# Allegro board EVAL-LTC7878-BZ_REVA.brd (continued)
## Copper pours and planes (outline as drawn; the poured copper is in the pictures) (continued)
UNNAMED_4_IND_I84_N1 on TOP: 96.2,88.98 96.22,89.01 96.25,89.03 96.85,89.03 96.89,89.01 96.9,88.98 96.9,87.94 96.89,87.9 96.85,87.88 96.25,87.88 96.22,87.9 96.2,87.94
UNNAMED_4_IND_I84_N1 on TOP, BOTTOM: 95.76,111.12 95.76,93.6 83.44,93.6 83.44,111.12
UNNAMED_4_NCTESTPAD_I106_N1 on TOP: 105.76,72.26 107.6,72.26
UNNAMED_4_RES_I65_N1 on TOP: 72.01,97.36 72.02,97.39 72.06,97.41 73.36,97.41 73.39,97.39 73.41,97.36 73.41,95.17 73.39,95.14 73.36,95.12 72.06,95.12 72.02,95.14 72.01,95.17
UNNAMED_4_RES_I79_N1 on TOP: 112.01,96.47 112.03,96.51 112.06,96.52 113.26,96.52 113.28,96.52 113.3,96.51 113.52,96.28 113.53,96.26 113.54,96.24 113.54,95.3 113.52,95.26 113.49,95.25 112.06,95.25 112.03,95.26 112.01,95.3
UNNAMED_4_RES_I108_N1 on TOP: 115.14,98.17 115.17,98.16 115.19,98.12 115.19,97.56 115.19,97.54 115.17,97.52 114.31,96.66 114.3,96.65 114.28,96.65 113.84,96.65 113.81,96.66 113.79,96.7 113.79,98.12 113.81,98.16 113.84,98.17
UNNAMED_4_RES_I108_N1 on TOP: 114.38,103.76 114.41,103.74 114.43,103.71 114.43,102.54 114.41,102.5 114.38,102.49 113.72,102.49 113.68,102.5 113.67,102.54 113.67,103.71 113.68,103.74 113.72,103.76
UNNAMED_5_ADLTC7878V2_I47_BG1 on TOP: 73.1,33.91 73.14,33.89 73.15,33.86 73.15,32.69 73.14,32.65 73.1,32.64 72.19,32.64 72.15,32.65 72.14,32.69 72.14,33.86 72.15,33.89 72.19,33.91
UNNAMED_5_ADLTC7878V2_I47_BG2 on TOP: 106.48,32.64 106.44,32.65 106.43,32.69 106.43,33.86 106.44,33.89 106.48,33.91 107.14,33.91 107.17,33.89 107.19,33.86 107.19,32.69 107.17,32.65 107.14,32.64
UNNAMED_5_ADLTC7878V2_I47_BOOST1 on TOP: 92.2,24.21 92.22,24.24 92.25,24.26 93.58,24.26 93.6,24.25 93.61,24.24 93.71,24.14 93.73,24.13 93.75,24.13 94.49,24.13 94.51,24.13 94.53,24.12 94.73,23.92 94.74,23.9 94.74,23.88 94.74,23.29 94.73,23.26 94.69,23.24 94.13,23.24 94.11,23.24 94.09,23.26 93.87,23.48 93.85,23.49 93.83,23.5 92.25,23.5 92.22,23.51 92.2,23.55
UNNAMED_5_ADLTC7878V2_I47_CSN on TOP: 102.86,24.38 104.66,24.38
UNNAMED_5_ADLTC7878V2_I47_CSP on TOP: 104.27,22.1 104.27,20.32 102.11,20.32 101.73,20.7 101.73,21.34 102.11,21.72 103.38,21.72 103.38,22.1
UNNAMED_5_ADLTC7878V2_I47_EXTVCC on TOP: 89.41,18.36 89.42,18.4 89.46,18.41 91.13,18.41 91.15,18.41 91.17,18.4 91.3,18.27 91.31,18.26 91.31,18.24 91.31,17.27 90.81,16.76 90.81,15.88 90.04,15.88 90.04,16.89 89.46,16.89 89.42,16.91 89.41,16.94
UNNAMED_5_ADLTC7878V2_I47_EXTVCC on TOP: 77.31,19.3 79.16,19.3
UNNAMED_5_ADLTC7878V2_I47_ISNSD on TOP: 95.83,25.4 95.87,25.39 95.89,25.35 95.89,24.31 95.87,24.27 95.83,24.26 95.53,24.26 95.51,24.26 95.49,24.27 95.07,24.69 95.06,24.7 95.06,24.72 95.06,25.35 95.07,25.39 95.11,25.4
UNNAMED_5_ADLTC7878V2_I47_ITHB on TOP: 97.66,13.28 97.68,13.32 97.71,13.34 98.37,13.34 98.41,13.32 98.42,13.28 98.42,12.47 98.42,12.45 98.41,12.44 98.18,12.21 98.17,12.2 98.15,12.19 97.71,12.19 97.68,12.21 97.66,12.24
UNNAMED_5_ADLTC7878V2_I47_MODE on TOP: 104.39,15.95 104.41,15.99 104.44,16 105.36,16 105.4,15.99 105.41,15.95 105.41,15.35 105.4,15.32 105.36,15.3 104.44,15.3 104.41,15.32 104.39,15.35
UNNAMED_5_ADLTC7878V2_I47_PGOOD on TOP: 95.63,13.28 95.65,13.32 95.68,13.34 96.34,13.34 96.38,13.32 96.39,13.28 96.39,12.24 96.38,12.21 96.34,12.19 95.68,12.19 95.65,12.21 95.63,12.24
UNNAMED_5_ADLTC7878V2_I47_PGOOD on TOP: 77.18,10.79 79.03,10.79
UNNAMED_5_ADLTC7878V2_I47_PHASMD on TOP: 104.39,16.97 104.41,17 104.44,17.02 105.36,17.02 105.4,17 105.41,16.97 105.41,16.31 105.4,16.27 105.36,16.26 104.44,16.26 104.41,16.27 104.39,16.31
UNNAMED_5_ADLTC7878V2_I47_SETCUR on TOP: 101.73,20.02 101.74,20.05 101.78,20.07 102.95,20.07 102.98,20.05 103,20.02 103,19.36 102.98,19.32 102.95,19.3 101.78,19.3 101.74,19.32 101.73,19.36
UNNAMED_5_ADLTC7878V2_I47_SW1 on TOP: 94.61,27.64 94.63,27.67 94.67,27.69 95.77,27.69 95.81,27.67 95.82,27.64 95.82,26.85 95.81,26.81 95.77,26.8 94.89,26.8 94.87,26.8 94.85,26.81 94.63,27.04 94.62,27.05 94.61,27.07
UNNAMED_5_ADLTC7878V2_I47_SW1 on TOP: 93.34,25.22 93.36,25.26 93.4,25.27 94.75,25.27 94.79,25.26 94.8,25.22 94.8,24.62 94.81,24.6 94.82,24.58 94.85,24.55 94.87,24.53 94.87,24.51 94.87,24.44 94.85,24.4 94.82,24.38 93.85,24.38 93.83,24.39 93.82,24.4 93.72,24.5 93.7,24.51 93.68,24.51 93.4,24.51 93.36,24.53 93.34,24.56
UNNAMED_5_ADLTC7878V2_I47_SW1 on TOP: 74.16,42.77 74.18,42.79 74.2,42.8 77.55,42.8 77.58,42.78 77.6,42.75 77.6,41.07 77.61,41.04 77.65,41.02 79.35,41.02 79.37,41.02 79.39,41.04 79.87,41.51 79.88,41.53 79.9,41.53 80.52,41.53 80.52,44.32 82.93,44.32 82.93,32.64 73.66,32.64 73.66,40.75 73.66,40.79 73.66,41.91 73.71,41.91 74.04,42.08 74.17,42.42 74.15,42.54 74.11,42.65 74.11,42.66 74.11,42.69
UNNAMED_5_ADLTC7878V2_I47_SW1 on BOTTOM: 75.31,42.75 75.33,42.78 75.36,42.8 78.71,42.8 78.73,42.79 78.75,42.77 78.8,42.69 78.8,42.66 78.8,42.65 78.75,42.54 78.74,42.42 78.89,42.06 79.25,41.91 79.42,41.94 79.57,42.03 79.59,42.04 79.63,42.04 82.93,42.04 82.93,32.64 73.84,32.64 73.8,32.65 73.79,32.69 73.79,40.97 73.8,41.01 73.84,41.02 75.26,41.02 75.3,41.04 75.31,41.07
UNNAMED_5_ADLTC7878V2_I47_SW1 on LAYER_2: 71.37,41.02 71.37,32 79.38,32 79.38,41.02
UNNAMED_5_ADLTC7878V2_I47_SW1 on LAYER_3: 79.38,32 79.38,40.64 71.63,40.64 71.63,32
UNNAMED_5_ADLTC7878V2_I47_SW1 on LAYER_4, LAYER_5, LAYER_6: 79.38,31.88 79.38,40.89 71.63,40.89 71.63,31.88
UNNAMED_5_ADLTC7878V2_I47_SW1 on LAYER_7: 79.38,31.88 79.38,40.64 71.63,40.64 71.63,31.88
UNNAMED_5_ADLTC7878V2_I47_SW2 on TOP: 113.28,50.16 113.28,41.2 113.3,41.16 113.33,41.15 115.27,41.15 115.3,41.13 115.32,41.1 115.32,37.47 113.54,37.47 113.54,37.47 113.28,37.47 113.28,35.94 106.05,35.94 106.05,32.64 97.41,32.64 97.41,50.16
UNNAMED_5_ADLTC7878V2_I47_SW2 on TOP: 94.52,13.33 94.54,13.34 95.33,13.34 95.36,13.32 95.38,13.28 95.38,11.99 95.36,11.95 95.33,11.94 94.54,11.94 94.5,11.95 94.49,11.99 94.49,13.28 94.49,13.3
UNNAMED_5_ADLTC7878V2_I47_SW2 on TOP: 99.44,26.72 99.43,26.68 99.39,26.67 98.73,26.67 98.69,26.68 98.68,26.72 98.68,28.14 98.69,28.18 98.73,28.19 99.39,28.19 99.43,28.18 99.44,28.14
UNNAMED_5_ADLTC7878V2_I47_SW2 on BOTTOM: 113.28,50.16 113.28,40.01 115.32,40.01 115.32,36.58 114.68,35.94 106.93,35.94 106.93,32.64 97.41,32.64 97.41,50.16
UNNAMED_5_ADLTC7878V2_I47_SW2 on LAYER_2, LAYER_3, LAYER_5, LAYER_6, LAYER_7: 105.28,45.21 105.28,36.2 113.28,36.2 113.28,45.21
UNNAMED_5_ADLTC7878V2_I47_SW2 on LAYER_4: 107.82,41.53 107.82,34.04 113.28,34.04 113.28,41.53
UNNAMED_5_ADLTC7878V2_I47_TG1 on TOP: 79.5,44.27 79.52,44.31 79.55,44.32 80.21,44.32 80.25,44.31 80.26,44.27 80.26,43.1 80.25,43.07 80.21,43.05 79.55,43.05 79.52,43.07 79.5,43.1
UNNAMED_5_ADLTC7878V2_I47_TG2 on TOP: 113.67,44.27 113.68,44.31 113.72,44.32 114.38,44.32 114.41,44.31 114.43,44.27 114.43,43.1 114.41,43.07 114.38,43.05 113.72,43.05 113.68,43.07 113.67,43.1
UNNAMED_5_ADLTC7878V2_I47_VOUT on TOP: 99.19,24.71 99.2,24.75 99.24,24.77 100.66,24.77 100.7,24.75 100.71,24.71 100.71,23.93 100.7,23.89 100.66,23.88 99.24,23.88 99.2,23.89 99.19,23.93
UNNAMED_5_CAP_I33_N1 on TOP: 97.66,9.73 97.68,9.76 97.71,9.78 99.39,9.78 99.43,9.76 99.44,9.73 99.44,8.94 99.43,8.9 99.39,8.89 97.71,8.89 97.68,8.9 97.66,8.94
UNNAMED_5_CAP_I94_N2 on TOP: 104.52,23.11 104.52,21.34 105.41,21.34 105.41,22.23 106.43,22.23 106.43,23.11
UNNAMED_5_CAP_I94_N2 on TOP: 105.78,24.38 107.58,24.38
UNNAMED_5_IND_I85_N1 on TOP: 96.2,28.02 96.22,28.05 96.25,28.07 96.85,28.07 96.89,28.05 96.9,28.02 96.9,26.98 96.89,26.94 96.85,26.92 96.25,26.92 96.22,26.94 96.2,26.98
UNNAMED_5_IND_I85_N1 on TOP: 95.76,50.16 95.76,32.69 95.74,32.65 95.71,32.64 83.44,32.64 83.44,50.16
UNNAMED_5_IND_I85_N1 on BOTTOM: 95.76,50.16 95.76,32.64 83.44,32.64 83.44,50.16
UNNAMED_5_NCTESTPAD_I107_N1 on TOP: 105.76,11.3 107.6,11.3
UNNAMED_5_RES_I66_N1 on TOP: 72.01,36.4 72.02,36.43 72.06,36.45 73.36,36.45 73.39,36.43 73.41,36.4 73.41,34.21 73.39,34.18 73.36,34.16 72.06,34.16 72.02,34.18 72.01,34.21
UNNAMED_5_RES_I80_N1 on TOP: 112.01,35.51 112.03,35.55 112.06,35.56 113.26,35.56 113.28,35.56 113.3,35.55 113.52,35.32 113.53,35.3 113.54,35.28 113.54,34.34 113.52,34.3 113.49,34.29 112.06,34.29 112.03,34.3 112.01,34.34
UNNAMED_5_RES_I109_N1 on TOP: 114.38,42.8 114.41,42.78 114.43,42.75 114.43,41.58 114.41,41.54 114.38,41.53 113.72,41.53 113.68,41.54 113.67,41.58 113.67,42.75 113.68,42.78 113.72,42.8
UNNAMED_5_RES_I109_N1 on TOP: 115.14,37.21 115.17,37.2 115.19,37.16 115.19,36.6 115.19,36.58 115.17,36.56 114.31,35.7 114.3,35.69 114.28,35.69 113.84,35.69 113.81,35.7 113.79,35.74 113.79,37.16 113.81,37.2 113.84,37.21
UNNAMED_6_ADLT3014V2_I44_ADJ on TOP: 137.48,126.87 137.35,126.75 137.35,125.67 137.16,125.48 137.16,123.7 138.05,123.7 138.05,126.24 138.94,126.24 138.94,126.87
UNNAMED_6_ADLTC6909_I1_SET on TOP: 131.83,133.48 131.83,131.95 133.35,131.95 133.35,133.48
VAUX on TOP: 128.91,136.27 130.05,136.27 130.3,136.02 130.3,135.64 130.05,135.38 129.79,135.38 129.79,133.48 131.57,131.7 135.51,131.7 135.51,134.24 135,134.24 135,134.49 136.4,134.49 136.65,134.24 139.19,134.24 139.19,135.13 141.6,135.13 141.6,127.89 139.19,127.89 138.94,128.14 137.41,128.14 137.35,128.21 137.35,128.71 137.41,128.78 138.94,128.78 139.19,129.03 139.19,130.94 131.19,130.94 128.91,133.22
VAUX on TOP: 136.02,124.46 136.02,123.32 136.91,123.32 136.91,124.46
VAUX on TOP: 133.6,133.48 133.6,131.95 135.13,131.95 135.13,133.48
VFB_1 on TOP: 115.23,257.18 117.18,257.18
VFB_2 on TOP: 115.23,196.22 117.18,196.22
VFB_3 on TOP: 115.23,135.25 117.18,135.25
VFB_4 on TOP: 115.23,74.3 117.18,74.3
VFB_5 on TOP: 115.23,15.24 117.18,15.24
VOUT on TOP: 129.54,284.92 129.54,278.26 130.56,278.26 130.56,284.92
VOUT on TOP: 129.54,102.04 129.54,95.38 130.56,95.38 130.56,102.04
VOUT on TOP: 115.7,47.45 115.71,47.48 115.75,47.5 129.67,47.5 129.67,33.27 114.19,33.27 114.17,33.28 114.16,33.29 113.81,33.64 113.8,33.66 113.79,33.68 113.79,34.04 113.79,35.38 113.81,35.42 113.84,35.43 114.41,35.43 114.53,35.43 114.55,35.44 114.57,35.45 115.68,36.56 115.69,36.58 115.7,36.6
VOUT on TOP: 170.18,291.34 170.18,200.66 182.88,200.66 182.88,151.76 170.18,151.76 170.18,33.27 130.43,33.27 130.43,47.5 145.41,47.5 145.41,94.23 130.43,94.23 130.43,108.46 145.41,108.46 145.41,155.19 130.43,155.19 130.43,169.42 145.41,169.42 145.41,216.15 130.43,216.15 130.43,230.38 145.41,230.38 145.41,277.11 130.43,277.11 130.43,291.34
VOUT on TOP: 108.88,72.26 110.83,72.26
VOUT on TOP: 115.7,291.29 115.71,291.32 115.75,291.34 129.67,291.34 129.67,277.11 114.19,277.11 114.17,277.12 114.16,277.13 113.81,277.48 113.8,277.5 113.79,277.52 113.79,277.88 113.79,279.22 113.81,279.26 113.84,279.27 114.41,279.27 114.53,279.27 114.55,279.28 114.57,279.29 115.68,280.4 115.69,280.42 115.7,280.44
VOUT on TOP: 129.54,223.96 129.54,217.3 130.56,217.3 130.56,223.96
VOUT on TOP: 115.7,108.41 115.71,108.44 115.75,108.46 129.67,108.46 129.67,94.23 114.19,94.23 114.17,94.24 114.16,94.25 113.81,94.6 113.8,94.62 113.79,94.64 113.79,95 113.79,96.34 113.81,96.38 113.84,96.39 114.41,96.39 114.53,96.39 114.55,96.4 114.57,96.41 115.68,97.52 115.69,97.54 115.7,97.56
VOUT on TOP: 108.88,255.14 110.83,255.14
VOUT on TOP: 115.7,230.33 115.71,230.36 115.75,230.38 129.67,230.38 129.67,216.15 114.19,216.15 114.17,216.16 114.16,216.17 113.81,216.52 113.8,216.54 113.79,216.56 113.79,216.92 113.79,218.26 113.81,218.3 113.84,218.31 114.41,218.31 114.53,218.31 114.55,218.32 114.57,218.33 115.68,219.44 115.69,219.46 115.7,219.48
VOUT on TOP: 108.88,133.22 110.83,133.22
VOUT on TOP: 129.54,163 129.54,156.34 130.56,156.34 130.56,163
VOUT on TOP: 129.54,41.08 129.54,34.42 130.56,34.42 130.56,41.08
VOUT on TOP: 115.7,169.37 115.71,169.4 115.75,169.42 129.67,169.42 129.67,155.19 114.19,155.19 114.17,155.2 114.16,155.21 113.81,155.56 113.8,155.58 113.79,155.6 113.79,155.96 113.79,157.3 113.81,157.34 113.84,157.35 114.41,157.35 114.53,157.35 114.55,157.36 114.57,157.37 115.68,158.48 115.69,158.5 115.7,158.52
VOUT on TOP: 108.88,11.3 110.83,11.3
VOUT on TOP: 101.09,269.75 101.09,268.86 99.95,268.86 99.95,269.75
VOUT on TOP: 108.88,194.18 110.83,194.18
VOUT on BOTTOM: 115.7,47.45 115.71,47.48 115.75,47.5 129.79,47.5 129.79,33.27 114.32,33.27 114.3,33.28 114.29,33.29 113.81,33.77 113.8,33.78 113.79,33.8 113.79,34.52 113.79,34.57 113.79,35.35 113.8,35.37 113.81,35.39 113.88,35.45 113.91,35.45 113.98,35.44 114.05,35.43 114.29,35.49 114.49,35.68 114.51,35.69 114.79,35.69 114.81,35.69 114.82,35.7 115.68,36.56 115.69,36.58 115.7,36.6
VOUT on BOTTOM: 129.79,291.34 129.79,277.11 114.32,277.11 114.3,277.12 114.29,277.13 113.79,277.62 113.79,278.36 113.79,278.41 113.79,279.19 113.8,279.21 113.81,279.23 113.88,279.29 113.91,279.29 113.98,279.28 114.05,279.27 114.29,279.33 114.49,279.52 114.51,279.53 114.79,279.53 114.81,279.53 114.82,279.54 115.68,280.4 115.69,280.42 115.7,280.44 115.7,291.34
VOUT on BOTTOM: 130.3,291.34 170.18,291.34 170.18,200.66 182.88,200.66 182.88,151.76 170.18,151.76 170.18,34.16 130.3,34.16 130.3,47.5 145.41,47.5 145.41,95.12 130.3,95.12 130.3,108.46 145.41,108.46 145.41,156.08 130.3,156.08 130.3,169.42 145.41,169.42 145.41,217.04 130.3,217.04 130.3,230.38 145.41,230.38 145.41,278 130.3,278
VOUT on BOTTOM: 115.7,108.41 115.71,108.44 115.75,108.46 129.79,108.46 129.79,94.23 114.32,94.23 114.3,94.24 114.29,94.25 113.81,94.73 113.8,94.74 113.79,94.76 113.79,95.48 113.79,95.53 113.79,96.31 113.8,96.33 113.81,96.35 113.88,96.41 113.91,96.41 113.98,96.4 114.05,96.39 114.29,96.45 114.49,96.64 114.51,96.65 114.79,96.65 114.81,96.65 114.82,96.66 115.68,97.52 115.69,97.54 115.7,97.56
VOUT on BOTTOM: 115.7,230.33 115.71,230.36 115.75,230.38 129.79,230.38 129.79,216.15 114.32,216.15 114.3,216.16 114.29,216.17 113.81,216.65 113.8,216.66 113.79,216.68 113.79,217.4 113.79,217.45 113.79,218.23 113.8,218.25 113.81,218.27 113.88,218.33 113.91,218.33 113.98,218.32 114.05,218.31 114.29,218.37 114.49,218.56 114.51,218.57 114.79,218.57 114.81,218.57 114.82,218.58 115.68,219.44 115.69,219.46 115.7,219.48
VOUT on BOTTOM: 115.7,169.37 115.71,169.4 115.75,169.42 129.79,169.42 129.79,155.19 114.32,155.19 114.3,155.2 114.29,155.21 113.81,155.69 113.8,155.7 113.79,155.72 113.79,156.44 113.79,156.49 113.79,157.27 113.8,157.29 113.81,157.31 113.88,157.37 113.91,157.37 113.98,157.36 114.05,157.35 114.29,157.41 114.49,157.6 114.51,157.61 114.79,157.61 114.81,157.61 114.82,157.62 115.68,158.48 115.69,158.5 115.7,158.52
VOUT on LAYER_2: 132.84,307.59 132.84,8.76 171.45,8.76 171.45,150.62 182.88,150.62 182.88,202.44 171.45,202.44 171.45,307.59
VOUT on LAYER_2: 113.67,288.93 113.67,279.91 121.67,279.91 121.67,288.93
VOUT on LAYER_2, LAYER_3, LAYER_4, LAYER_5, LAYER_6, LAYER_7: 113.67,106.17 113.67,97.16 121.67,97.16 121.67,106.17
VOUT on LAYER_2, LAYER_3, LAYER_4, LAYER_5, LAYER_6, LAYER_7: 113.67,167.13 113.67,158.12 121.67,158.12 121.67,167.13
VOUT on LAYER_2, LAYER_3, LAYER_4, LAYER_5, LAYER_6, LAYER_7: 113.67,228.09 113.67,219.07 121.67,219.07 121.67,228.09
VOUT on LAYER_2, LAYER_3, LAYER_4, LAYER_5, LAYER_6, LAYER_7: 113.67,45.21 113.67,36.2 121.67,36.2 121.67,45.21
VOUT on LAYER_3: 113.54,289.05 113.54,280.04 121.54,280.04 121.54,289.05
VOUT on LAYER_4, LAYER_5, LAYER_6, LAYER_7: 113.67,289.05 113.67,280.04 121.67,280.04 121.67,289.05

Small or netless copper shapes (teardrops, artwork), in the pictures only: 139 on TOP, 47 on BOTTOM, 24 on LAYER_4, 25 on LAYER_5, 107 on LAYER_6

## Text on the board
User.Comments: STANDOFF (x8) | (8 PLACES) | JP3-JP4 INSTALL SHUNT ACROSS PINS 1-2 | JP1-JP2 INSTALL SHUNT ACROSS PINS 2-3 | JP5 INSTALL SHUNT ACROSS PINS 7-8
Ref Des/Silkscreen Top: 5.5kW | 70V PARALLELABLE FIVE-PHASE | 4-SWITCH BUCK-BOOST CONTROLLER | LTC7878 | EVAL-LTC7878-BZ
DIMENSION: FAB NOTES REVISION: 2ND NOVEMBER 2022 | 8.   IMPEDANCE REQUIREMENTS: IF NO STACKUP IS DEFINED, THE VENDOR IS ALLOWED TO ADJUST THE DIELECTRIC | 13.  PLATING SPECIFICATION: | 9.   FILLET OPTIONS TO ENHANCE RELIABILITY AT PAD JUNCTIONS WHERE SPACING PERMITS. | 10.  THIEVING: | 11.  LAYER TO LAYER REGISTRATION SHALL BE WITHIN 0.003 INCHES. | 12.  DRILL SIZES ARE FINISHED HOLE SIZES. ALL HOLES SHALL BE LOCATED WITHIN 0.005 INCHES DTP,UNLESS SPECIFIED. | 14.  SURFACE FINISH: | 15.  SOLDERMASK: | 1.   DIMENSIONS ARE IN INCHES (EXCEPT WHERE NOTED). | ALL DOCUMENTS & SPECIFICATIONS REFERRED TO BELOW SHOULD BE THE LATEST REVISIONS. | 2.  BOARD MATERIAL:(USE CHECKED ITEMS) | 3.   ALL LAMINATES & BONDING MATERIALS SHOULD BE SELECTED FROM IPC-4101 OR IPC-4103,(TG>170 DEGC TD>300 DEGC) | 4.   REFER TO IPC-6010 SERIES, CLASS 2 FOR FABRICATION. | 5.   REFER TO LAMINATION DIAGRAM FOR OVERALL BOARD THICKNESS, TOLERANCE APPLIES AFTER ALL LAMINATION AND PLATING | 6.   BOW & TWIST NOT TO EXCEED 0.0075 INCHES (0.75%) PER LINEAR INCH AND SHOULD BE MEASURED PER IPC-TM-650, METHOD 2.4.22. | 7.   ACCEPTABILITY PER ADI SPECIFICATION TST00115. | 16.  APPLY SILKSCREEN TO BOTH SIDES USING A NON-CONDUCTIVE, EPOXY BASED INK PER ARTWORK. | ( ) FILLETS ALLOWED | (X) FILLETS NOT ALLOWED | ( ) VENDOR MAY ADD THIEVING TO COMPENSATE FOR LOW COPPER DENSITY AREAS MAINTAINING A MINIMUM | (X) VENDOR MAY NOT ADD THIEVING TO COMPENSATE FOR LOW COPPER DENSITY AREAS. | (X) LPI | ( ) OTHER_________ | COLOR | ( ) GREEN | (X) OTHER_________ | (X) WHITE | HINDER PROPER SOLDER WICKING. BARREL RELIEF ON SOLDERMASK ALLOWED IN UNFILLED VIA IN PAD HOLES. | (X) REFER TO LAMINATION DIAGRAM FOR FINISHED COPPER WEIGHT/THICKNESS REQUIRMENTS | (X) IMMERSION GOLD (ENIG) 1.58-3.94 MICRO INCHES OVER 118-236 MICRO INCHES MIN. OF ELECTROLESS NICKEL PER IPC-4552 | ( ) OSP (ORGANIC SOLDERABILITY PRESERVATIVE) | ( ) IMMERSION SILVER | ( ) SOFT WIRE BONDABLE GOLD 30-50 MICRO INCHES OF SOFT WIRE | ( ) EDGE CONNECTOR FINGERS ARE TO BE PLATED WITH 100 MICRO-INCHES(.0001") OF LOW STRESS | THICKNESS & TRACE WIDTHS TO MEET THE IMPEDANCE REQUIREMENT. IF SPECIFIED, THE VENDOR MUST | TRACE WIDTH & SPACING THAT IMPACT THE REQUIREMENTS MUST HAVE WRITTEN APPROVAL FROM ADI. | MINIMUM BARREL PLATING OF 0.001 INCHES. PLATED HOLES SHALL NOT BE ROUGH OR IRREGULAR SO AS TO | SOLDERMASK OVER BARE COPPER OR BARE GOLD (BOTH SIDES) TO MEET IPC-SM-840. | IF PRESENT,DO NOT MODIFY SOLDERMASK DEFINED PADS (MASK OPENINGS LESS THAN COPPER PAD) WITHOUT APPROVAL. | MEET THE REQUIREMENTS LISTED IN THE IMPEDANCE TABLE. ANY ADJUSTMENT MADE TO THE DEFINED STACKUP, | PROCESSES. FINISHED THICKNESS MEASURED FROM TOP COPPER TO BOTTOM COPPER. | (X)  ISOLA 370HR OR S1000-2 OR IT180 OR EQUIVALENT | ( )  ISOLA-FR408HR OR EQUIVALENT | ( )  ISOLA IS410 | ( )  MEGTRON 6 | ( )  NELCO-4000-13 | ( )  ROGERS 4350B | ( ) ROGERS 3003 | ( ) ARLON 85N | ( ) EM370D | ( )  OTHER ________________________ | UL FLAMMABILITY RATING 94V-0. BOARD MATERIAL & CONSTRUCTION SHALL MEET THE REQUIREMENTS OF UL796/UL796F. | BONDABLE GOLD OVER 100-150 MICRO INCHES OF NICKEL | NICKEL UNDER 30 MICRO-INCHES (.0003') OF GOLD | 0.100 INCH CLEARANCE FROM ALL COPPER FEATURES, | THE STARTING COPPER WEIGHT/THICKNESS CAN VARY AS LONG AS THE FINISHED COPPER | WEIGHT/THICKNESS IS NOT LESS THAN THE SPECIFIED VALUE. | UNLESS OTHERWISE SPECIFIED | BLUE | HOMOGENOUS MATERIALS IN THIS BOARD SHALL BE COMPLAINT WITH THE EU DIRECTIVE 2002/95/EC | WORKMANSHIP SHALL CONFORM TO IPC-A-600, CLASS 2. | 21.  INTENTIONAL SHORTS: | 17.  FINAL ELECTRICAL TEST TO BE PERFORMED USING PROVIDED IPC-D-356A NETLIST OR ODB++ FORMAT FILE. | 22.  PEMNUTS: | 23.  MANUFACTURER TO ETCH/STAMP WITH PERMANENT NON-CONDUCTIVE INK | ON SECONDARY SIDE UNLESS OTHERWISE SPECIFIED: | 18.  A TIME DOMAIN REFLECTOMETER REPORT (TDR) FOR EACH IMPEDANCE CONTROLLED LAYER & A CERTIFICATE | 19.  IF PRESENT, ALL BLIND/BURIED VIAS WITH AN ASPECT RATIO <1:1 TO BE PLATED SHUT WITH COPPER WHEN | 20.  FOR VIA FILL INFORMATION REFER TO DRILL CHART: | 25. PANELIZATION: | 27.  MINIMUM DESIGN LINE WIDTH IS .006 INCH. | 28.  MINIMUM DESIGN LINE SPACING IS .006 INCH. | IS ACCEPTABLE, ALL OTHER INSTANCES MUST BE REPORTED. | IF AN INTENTIONAL SHORT REPORT IS SUPPLIED AND DOES NOT MATCH THE FAB DATA THEN | THE PCB SHALL HAVE A VERIFICATION STAMP. | (X)  NON-CONDUCTIVE EPOXY FILL ALL 0.012 INCHES DRILLED VIAS | ( )  COPPER FILL ALL 0.XXXX INCHES DRILLED VIAS | ( ) PEMNUTS TO BE INSTALLED BY FABRICATOR | ( ) PEMNUTS NOT TO BE INSTALLED BY FABRICATOR | (X) NOT APPLICABLE | USED AS VIA-IN-PAD OR AS A STACKED VIA. BLIND/BURIED VIAS WITH AN ASPECT RATIO >1:1 TO BE FILLED | A. UL CODE-FLAMMABILITY RATING FOR THOSE APPROVED MATERIALS(IF APPLICABLE) | B. DATE CODE | C. LOT NUMBER | D. MANUFACTURER LOGO | BOARDS TO BE SHIPPED IN ARRAY AND KEPT INTACT | PANEL TO BE SUBJECTED TO CUSTOMERS APPROVAL | PANEL SOLDER PASTE STENCIL GERBER TO BE PROVIDED TO ANALOG | CAN'T BE PERFORMED BECAUSE THE TRACE LENGTH IS TOO SHORT ON THE OUTER LAYERS AT THE PIN ESCAPES | ADI APPROVAL IS REQUIRED. | OF COMPLIANCE SHALL BE PROVIDED BY VENDOR AT TIME OF SHIPMENT. INSTANCES WHERE TDR TESTING | WITH NON-CONDUCTIVE EPOXY. | TOOLING: | FINISH: | NOTES: | MATERIAL: | TESTING: | MISCELLANEOUS: | "0" | SEE NOTE #20
User.24: IN | OUT | SUPPLY | POWER | V | I | LOAD | A | - | +
User.45: FIGURE | SIZE | 6.0 | 10.0 | 12.0 | 14.0 | 35.0 | 40.0 | 70.0 | 200.0 | 187.0 | PLATED | NON-PLATED | DRILL CHART: TOP to BOTTOM | ALL UNITS ARE IN MILS | QTY | 200 | 1350 | 320 | 1500 | 8 | 12 | 24 | TOLERANCE/NOTES
